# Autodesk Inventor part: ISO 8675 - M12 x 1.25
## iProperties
Created: 2005-05
Part Number: ISO 8675 - M12 x 1.25
Material: Standard
Description: Sechskantmutter
Vendor: Autodesk Inc.
Document SubType Name: Modeling
Standard: ISO 8675
Designer: tfa
Size Designation: M12 x 1.25
Author: tfa
Revision Number: 8
EGR: 2
Classification: un/spsc 31161727
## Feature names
1. Körper [Extrusion]
2. Fase1 [Revolution]
3. Gewinde [Hole]
4. Fase2 [Chamfer]
5. Fase3 [Chamfer]
